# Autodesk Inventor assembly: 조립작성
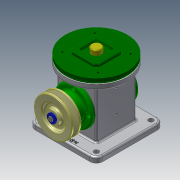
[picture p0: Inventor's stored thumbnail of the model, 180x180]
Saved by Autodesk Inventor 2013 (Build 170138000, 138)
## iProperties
Created: 2021-05
Part Number: 조립작성
Document SubType Name: Assembly
Designer: user
Author: user
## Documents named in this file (14)
- C:\Users\user\Desktop\710506V1020\조립작성.iam
- C:\Users\user\Desktop\710506V1020\본체.ipt
- C:\Users\user\Desktop\710506V1020\새 폴더\편심축.ipt
- C:\Users\user\Desktop\710506V1020\새 폴더\뒤커버.ipt
- C:\Users\user\Desktop\710506V1020\새 폴더\앞커버.ipt
- C:\Users\user\Desktop\710506V1020\새 폴더\키 4 x 4 x 12.ipt
- C:\Users\user\Desktop\710506V1020\새 폴더\오일 실 17 30 8.ipt
- C:\Users\user\Desktop\710506V1020\새 폴더\베어링 17 x 40 x 12.ipt
- C:\Users\user\Desktop\710506V1020\새 폴더\V-벨트풀리.ipt
- C:\Users\user\Desktop\710506V1020\새 폴더\와셔 4x16.ipt
- C:\Users\user\Desktop\710506V1020\새 폴더\볼트 M4 x 10.ipt
- C:\Users\user\Desktop\710506V1020\새 폴더\슬라이더.ipt
- C:\Users\user\Desktop\710506V1020\새 폴더\링크.ipt
- C:\Users\user\Desktop\710506V1020\새 폴더\덮개.ipt
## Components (1 placed, 1 different names)
1. V-벨트풀리:1
